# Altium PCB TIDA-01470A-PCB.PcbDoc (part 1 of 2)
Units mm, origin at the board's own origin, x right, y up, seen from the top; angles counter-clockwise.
Board outline 75 x 58 mm, 6 copper layers (Top Copper, Copper Layer 2, Copper Layer 3, Copper Layer 4, Copper Layer 5, Bottom Copper), stack 1.56 mm thick; 131 components, 70 nets, 308 pads, 94 vias.
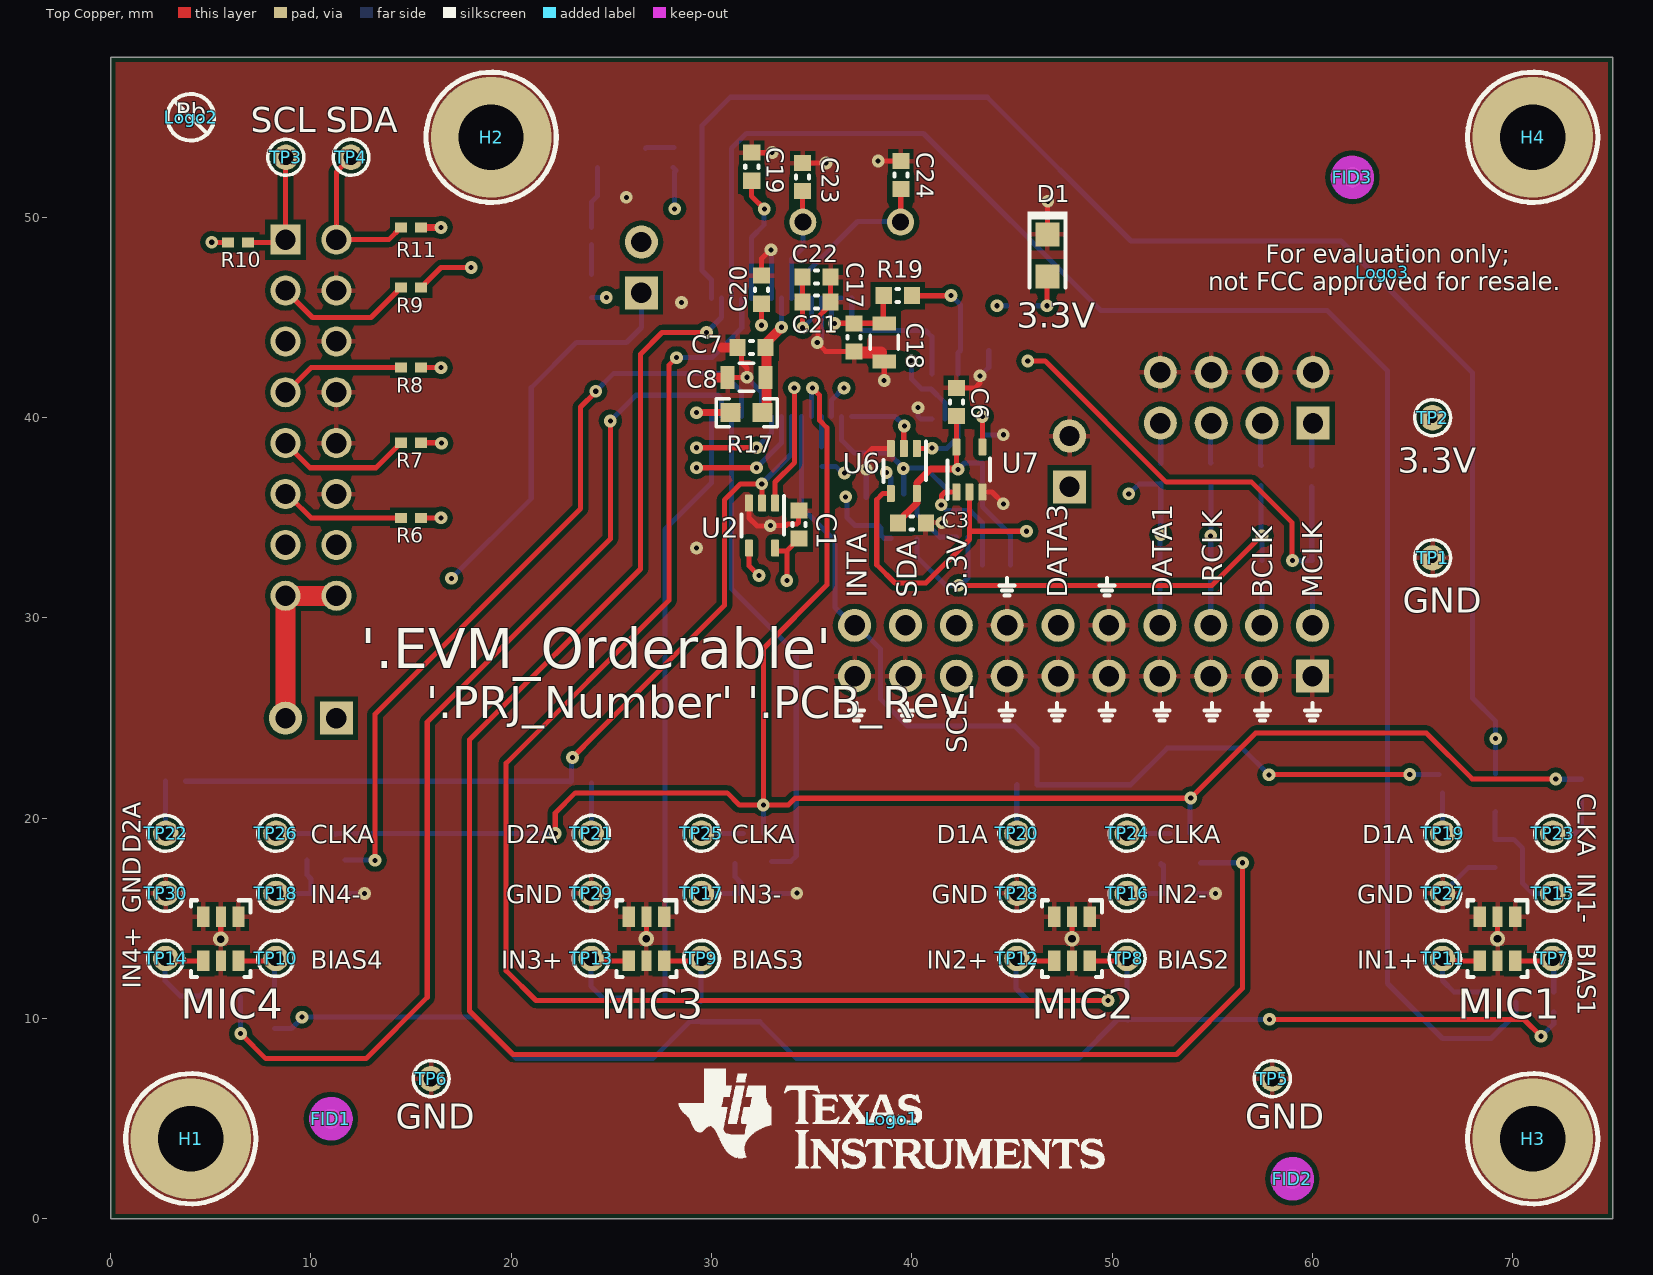
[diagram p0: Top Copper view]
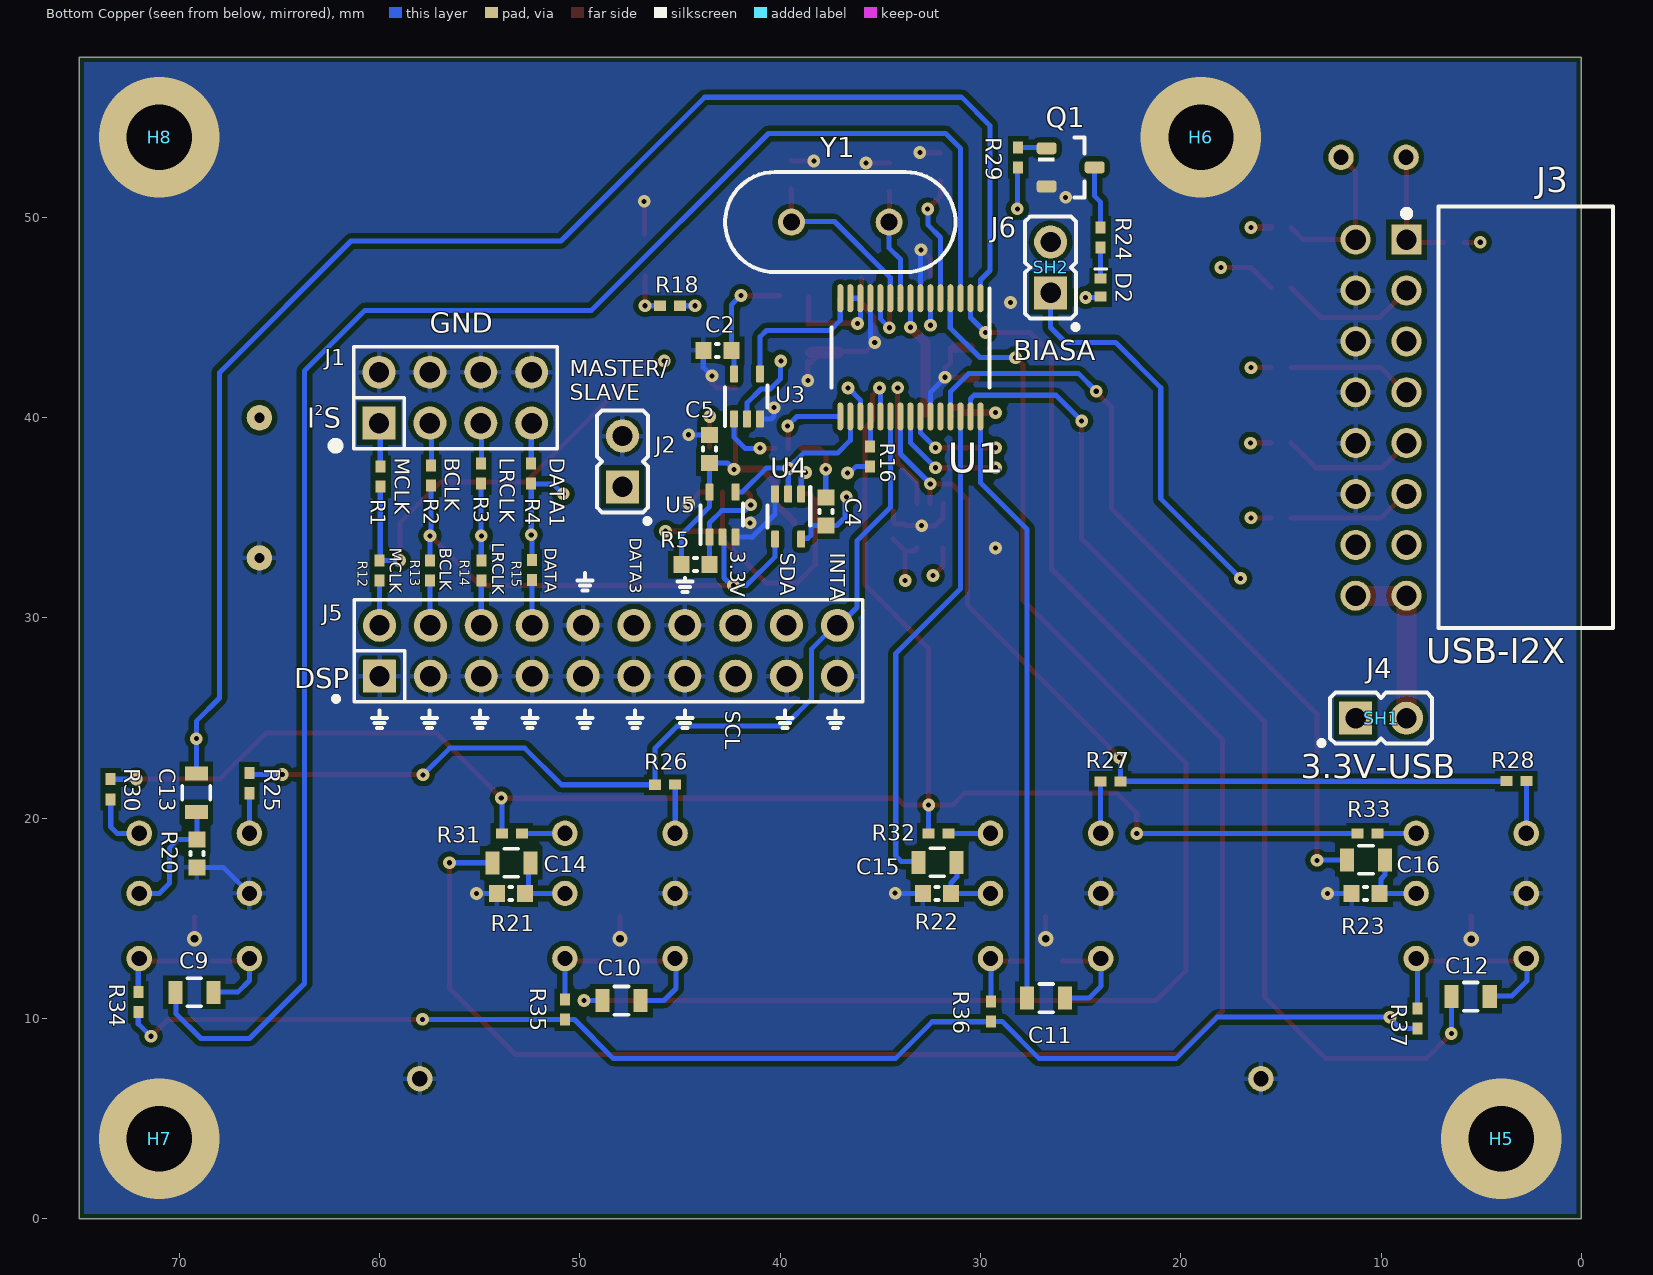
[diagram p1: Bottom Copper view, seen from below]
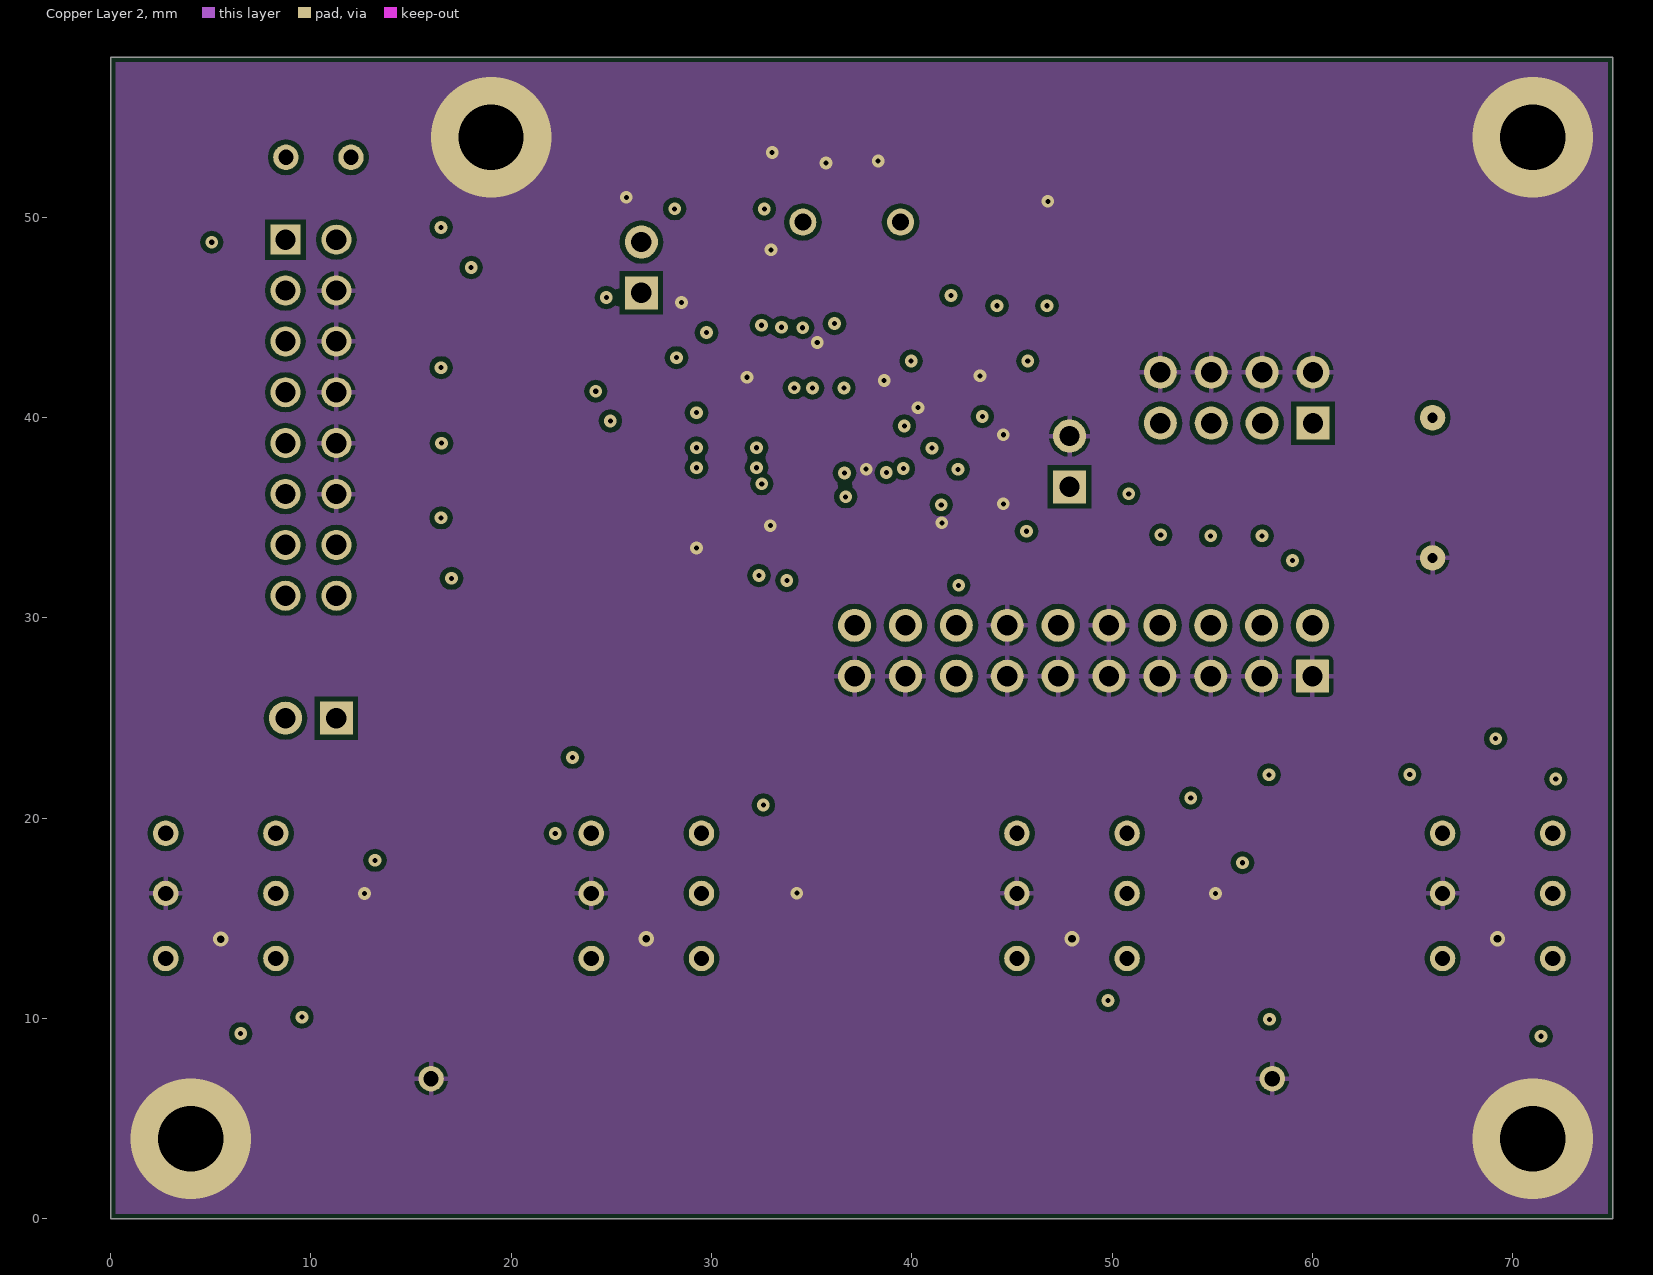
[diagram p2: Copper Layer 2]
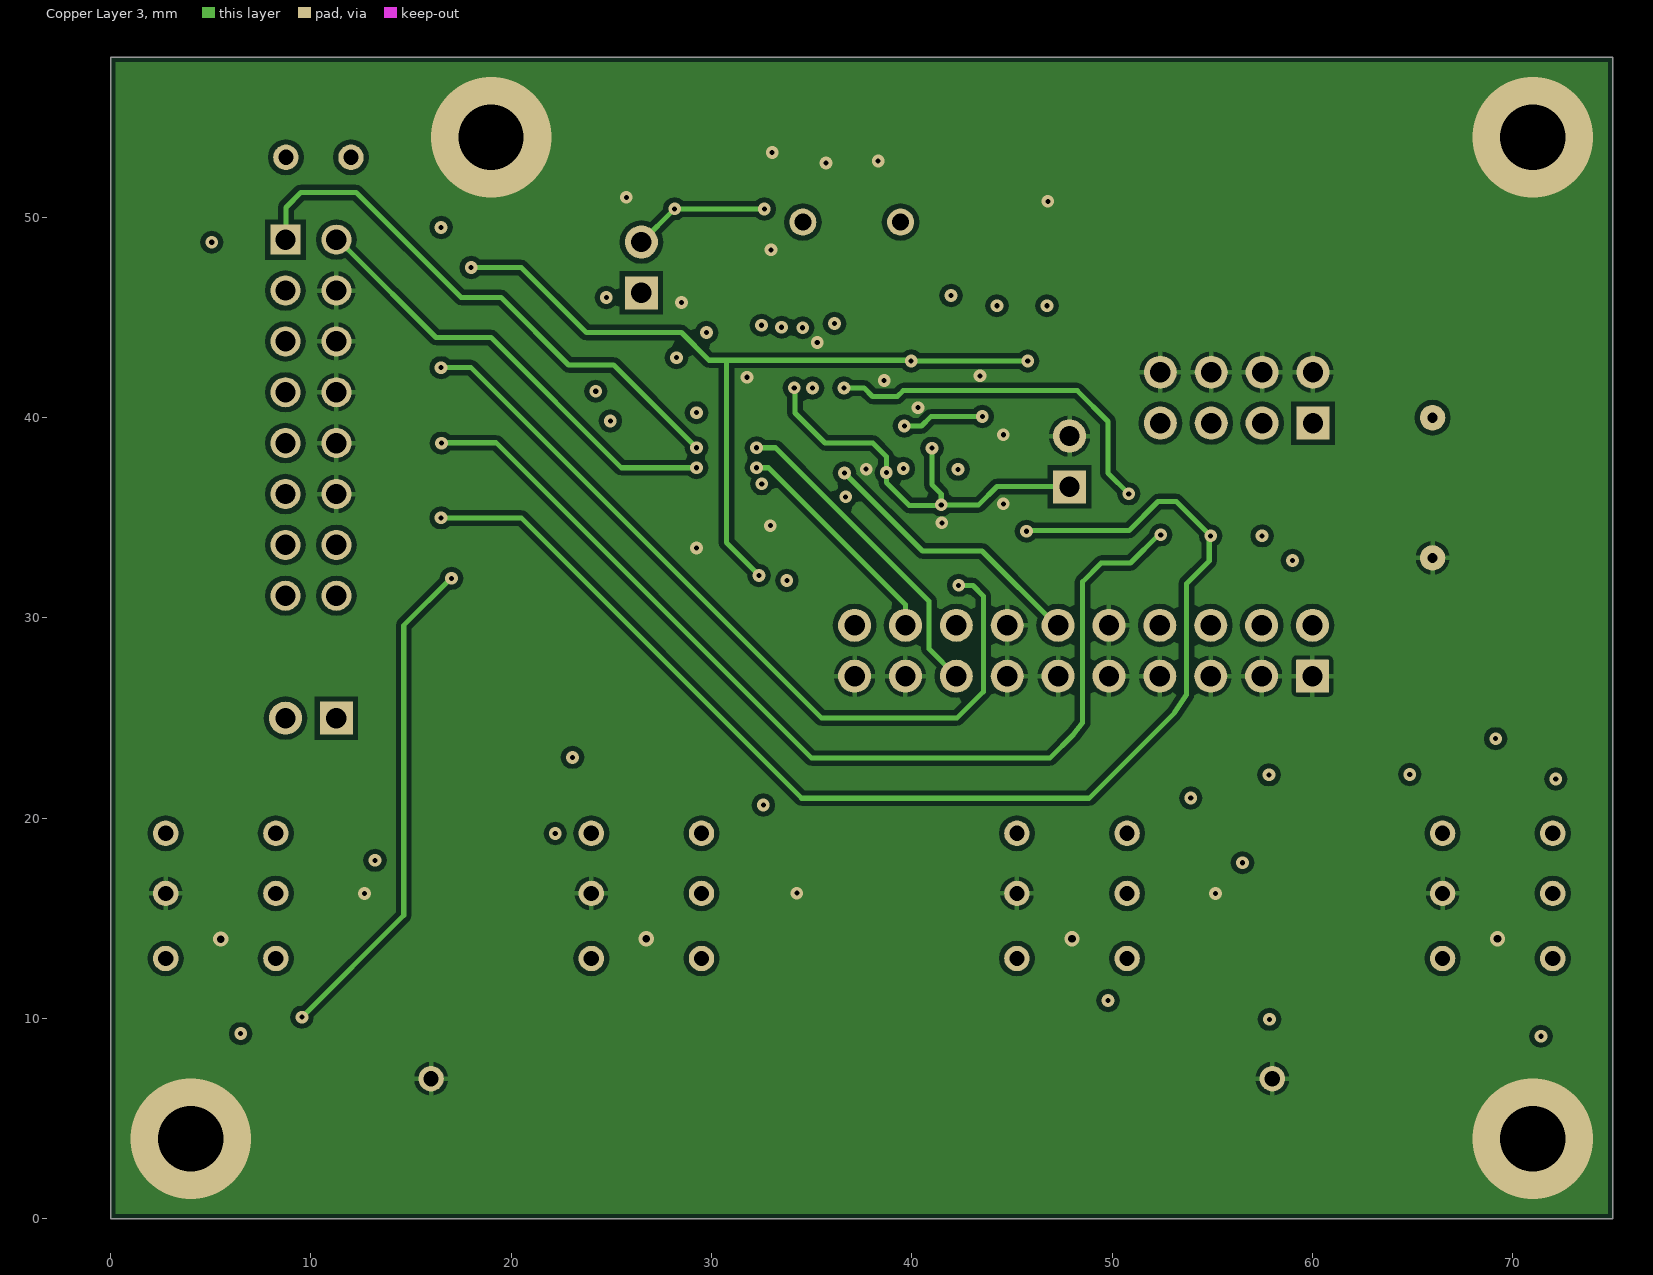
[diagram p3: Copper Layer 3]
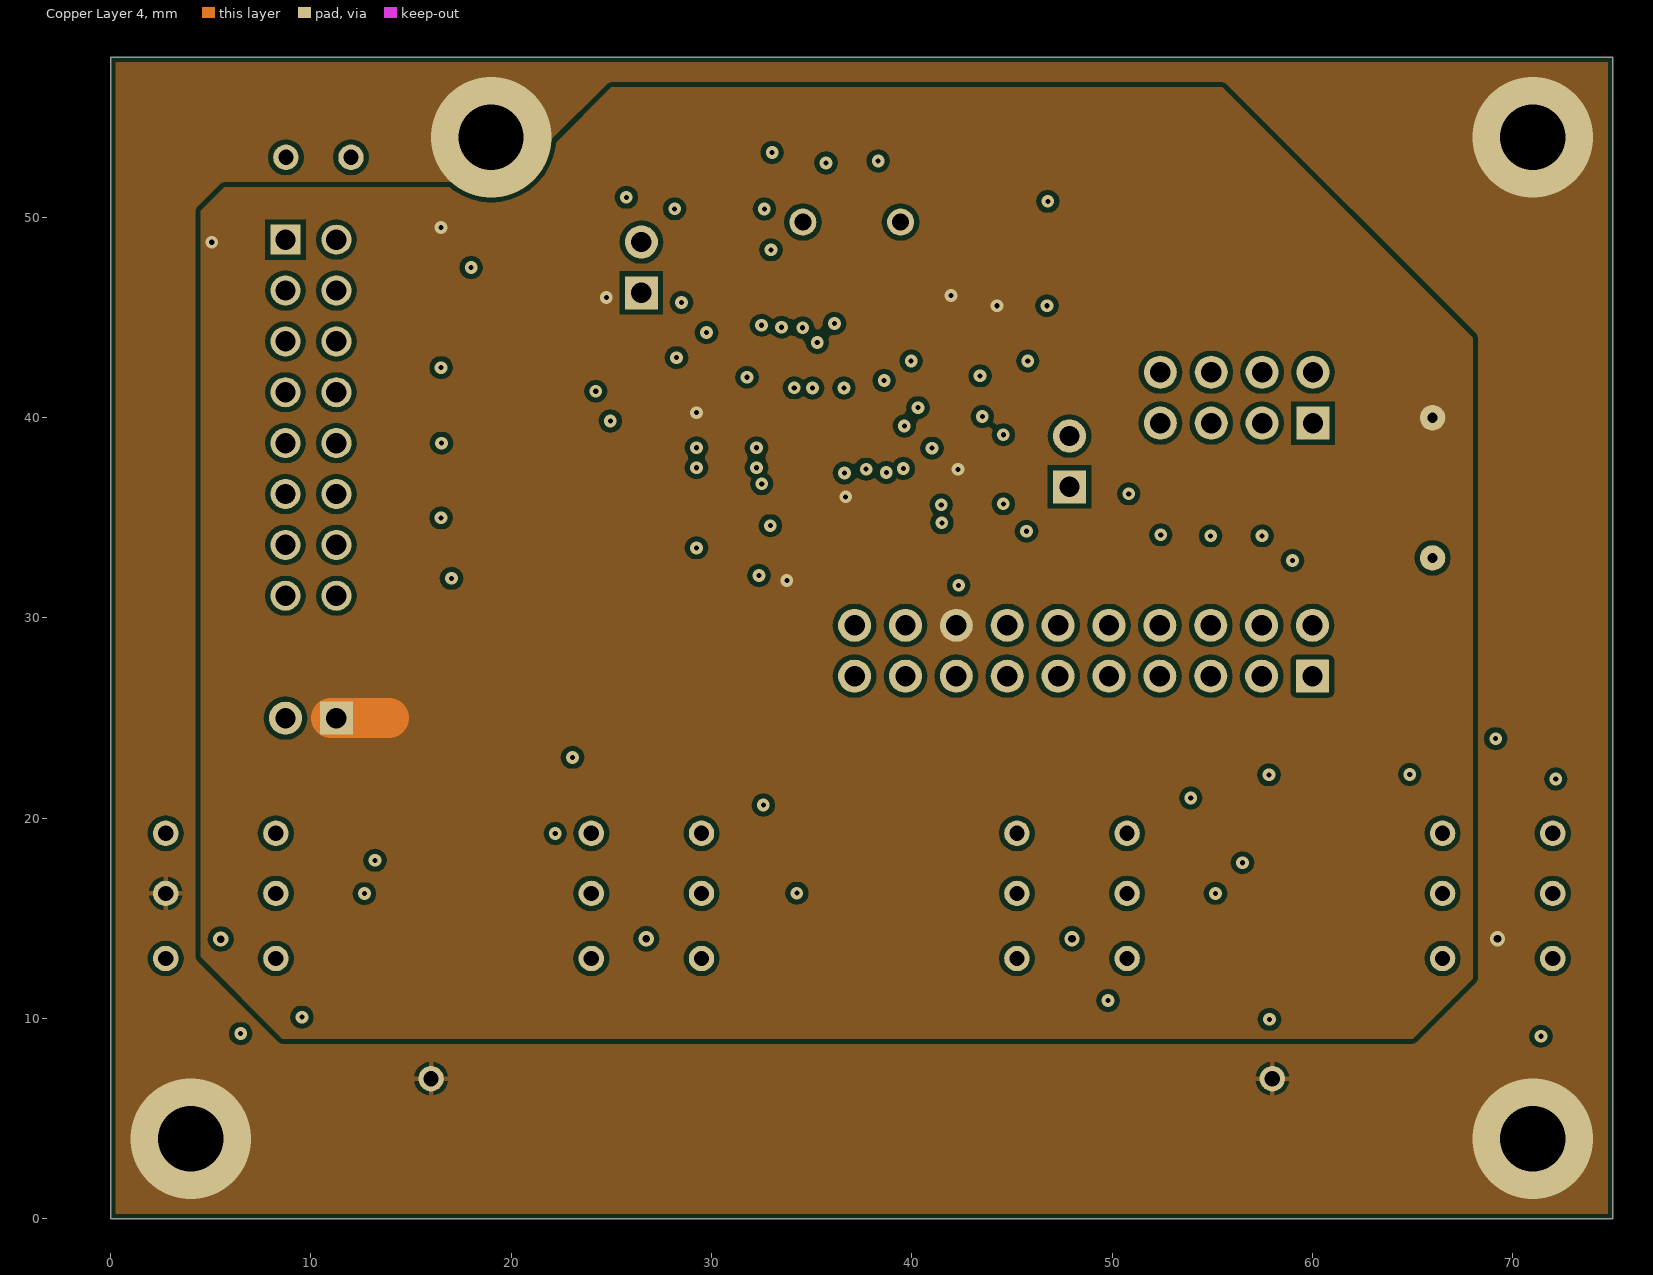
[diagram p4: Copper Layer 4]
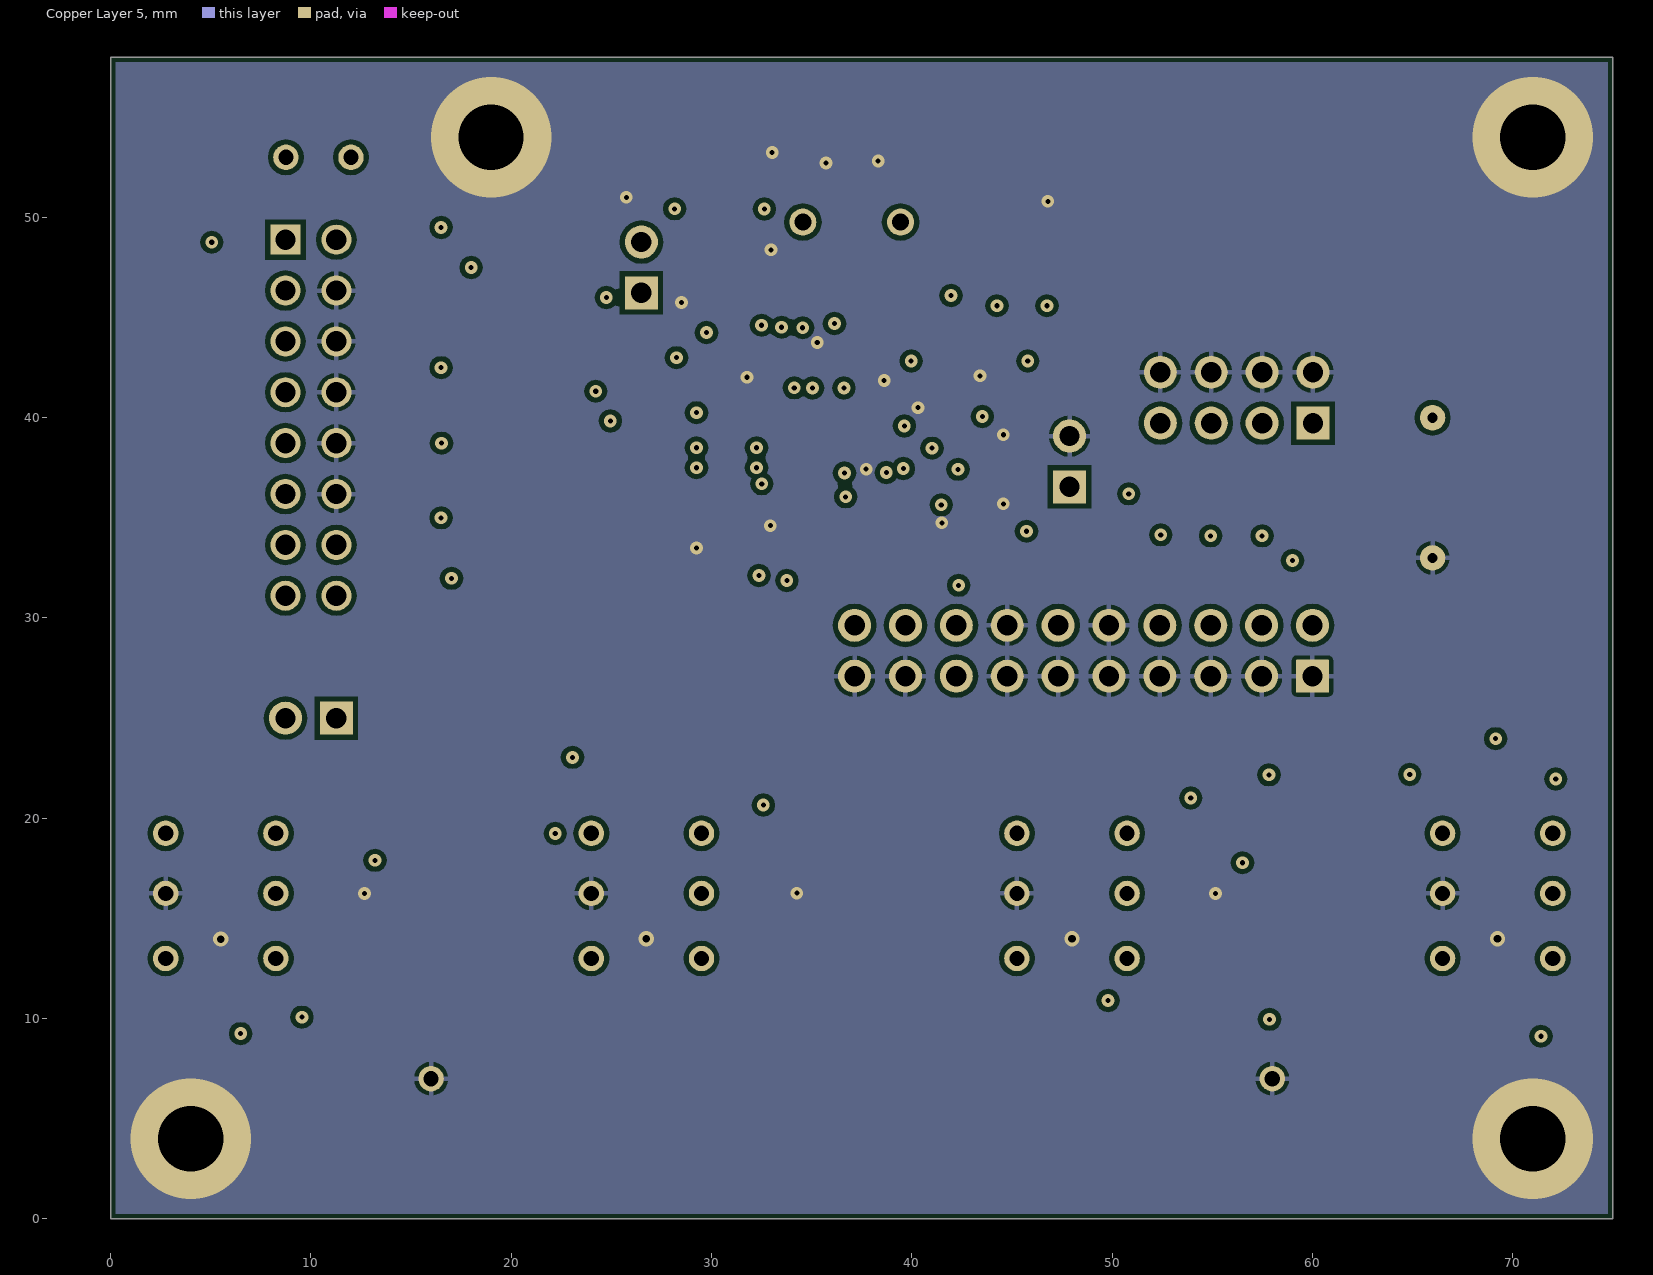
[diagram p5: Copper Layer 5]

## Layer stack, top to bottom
Top Solder Mask: solder mask 0.0127, Solder Resist, Dk 3.5
Top Copper: signal copper 0.0356
Dielectric 1: prepreg 0.1778, FR-4, Dk 4.2
Copper Layer 2: signal copper 0.0356
Dielectric 2: core 0.3556, FR-4, Dk 4.2
Copper Layer 3: signal copper 0.0356
Dielectric 4: prepreg 0.2794, FR-4, Dk 4.2
Copper Layer 4: signal copper 0.0356
Dielectric 5: core 0.3556, FR-4, Dk 4.2
Copper Layer 5: signal copper 0.0356
Dielectric 3: prepreg 0.1778, FR-4, Dk 4.2
Bottom Copper: signal copper 0.0356
Bottom Solder Mask: solder mask 0.0127, Solder Resist, Dk 3.5

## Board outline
0,0 75,0 75,58 0,58

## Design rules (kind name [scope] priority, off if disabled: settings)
AcuteAngle [All] p1: minimum=4.50000000000000E+0001 checktracksonly=FALSE
AssemblyTestPointUsage [All] p1: valid=2
BoardOutlineClearance BoardOutlineClearance_MountingHoles [OnCopper and InComponentClass('Mounting Holes')] p1: gap=1.016
BoardOutlineClearance BoardOutlineClearance_Poly [OnCopper and IsPoly] p2: gap=0.25
BoardOutlineClearance [OnCopper and Not InComponentClass('Logo') and not InComponentClass('FiducialMark') and not InRegion(1000,500,4000,800) and not InPoly] p3: gap=0.25
Clearance Clearance_Keepouts [((IsTrack Or IsArc) And Not InPoly) And IsFree and IsKeepOut vs ((IsTrack Or IsArc) And Not InPoly) And IsFree and IsKeepOut] p1: gap=0
Clearance Clearance_Poly [InPolygon] p2: gap=0.25
Clearance [All] p3: gap=0.2
ComponentClearance ComponentClearance_MountingHoles_FiducialMarks [InComponentClass('Mounting Holes') vs InComponentClass('FiducialMark')] p1: gap=1.27 collisioncheckmode=3 verticalgap=0.254 showdistances=FALSE
ComponentClearance ComponentClearance_Shunt [InComponentClass('Header') vs InComponentClass('Shunt')] p2: gap=0 collisioncheckmode=3 verticalgap=0 showdistances=FALSE
ComponentClearance ComponentClearance_Logo [InComponentClass('Logo')] p3: gap=0 collisioncheckmode=3 verticalgap=0 showdistances=FALSE
ComponentClearance ComponentClearance_ScrewToNut [(HasFootprint('NY PMS 440 0025 PH')) vs (HasFootprint('Keystone_1902C'))] p4: gap=0.127 collisioncheckmode=3 verticalgap=0.254 showdistances=FALSE
ComponentClearance ComponentClearance_MountingHoles [InComponentClass('Hardware') vs InComponentClass('Hardware')] p5: gap=0 collisioncheckmode=3 verticalgap=0 showdistances=FALSE
ComponentClearance ComponentClearance_SmallPassives [HasFootprint('0201*') or HasFootprint('0402*') or HasFootprint('0508') or HasFootprint('0603*') or HasFootprint('0612') or HasFootprint('0805*') or HasFootprint('0815*') or HasFootprint('0830*') or HasFootprint('1206*') or HasFootprint('1210*') or HasFootprint('1808*') or HasFootprint('1812*') or HasFootprint('1825*') or HasFootprint('2010*') or HasFootprint('2220*') or HasFootprint('2225*') or HasFootprint('2512*') or HasFootprint('2728*') or HasFootprint('3518*') or HasFootprint('DCK*') vs HasFootprint('0201*') or HasFootprint('0402*') or HasFootprint('0508') or HasFootprint('0603*') or HasFootprint('0612') or HasFootprint('0805*') or HasFootprint('0815*') or HasFootprint('0830*') or HasFootprint('1206*') or HasFootprint('1210*') or HasFootprint('1808*') or HasFootprint('1812*') or HasFootprint('1825*') or HasFootprint('2010*') or HasFootprint('2220*') or HasFootprint('2225*') or HasFootprint('2512*') or HasFootprint('2728*') or HasFootprint('3518*') or HasFootprint('DCK*')] p6: gap=0.25 collisioncheckmode=3 verticalgap=0 showdistances=FALSE
ComponentClearance ComponentClearance_THtoSMT [IsThruComponent vs IsSMTComponent] p7: gap=0.25 collisioncheckmode=3 verticalgap=0 showdistances=FALSE
ComponentClearance ComponentClearance_THtoTH [IsThruComponent vs IsThruComponent] p8: gap=0.762 collisioncheckmode=3 verticalgap=0.762 showdistances=FALSE
ComponentClearance [All] p9: gap=0.762 collisioncheckmode=3 verticalgap=0.254 showdistances=FALSE
DiffPairsRouting [All] p1: maxlimit=2.54 minlimit=0.254 mostfreqgap=0.254 toplayer_minwidth=0.381 toplayer_maxwidth=0.381 toplayer_prefwidth=0.381 midlayer1_minwidth=0.381 midlayer1_maxwidth=0.381 midlayer1_prefwidth=0.381 midlayer2_minwidth=0.381 midlayer2_maxwidth=0.381 midlayer2_prefwidth=0.381 midlayer3_minwidth=0.381 midlayer3_maxwidth=0.381 midlayer3_prefwidth=0.381 midlayer4_minwidth=0.381 midlayer4_maxwidth=0.381 midlayer4_prefwidth=0.381 bottomlayer_minwidth=0.381 bottomlayer_maxwidth=0.381 bottomlayer_prefwidth=0.381 maxuncoupledlength=25.4
FabricationTestPointUsage TestPointUsage [All] p1: valid=2 allowmultiple=FALSE
FabricationTestpoint Testpoint [All] p1: side=3 testpointundercomponent=TRUE minsize=1.016 maxsize=2.54 preferedsize=1.524 minholesize=0 maxholesize=1.016 preferedholesize=0.813 testpointgrid=0.025 allowsidetop=TRUE allowsidebottom=TRUE usegrid=TRUE gridtolerance=0
FanoutControl Fanout_LCC [IsLCC] p1: bgadir=Out bgaviamode=Centered fanoutstyle=Auto fanoutdirection=Alternating viagrid=0.025 // Fanout_LCC (Default Rule)
FanoutControl Fanout_BGA [IsBGA] p2: bgadir=Out bgaviamode=Centered fanoutstyle=Auto fanoutdirection=Alternating viagrid=0.025 // Fanout_BGA (Default Rule)
FanoutControl Fanout_Default [All] p4: bgadir=Out bgaviamode=Centered fanoutstyle=Auto fanoutdirection=Alternating viagrid=0.025 // Fanout_Default (Default Rule)
FanoutControl Fanout_Small [(CompPinCount < 5)] p5: bgadir=Out bgaviamode=Centered fanoutstyle=Auto fanoutdirection=OutThenIn viagrid=0.025 // Fanout_Small (Default Rule)
HoleSize [All] p1: absolutevalues=TRUE maxlimit=6.375 minlimit=0.2 maxpercent=80.000 minpercent=20.000
MinimumAnnularRing MinimumAnnularRing_ThermalPadVias [IsVia and InAnyComponent] p1: minimumring=0.15
MinimumAnnularRing [All] p2: minimumring=0.127
MinimumSolderMaskSliver MinimumSolderMaskSliver_Logo [InComponentClass('Logo') vs InComponentClass('Logo')] p1: minsoldermaskwidth=0.018
MinimumSolderMaskSliver [All] p2: minsoldermaskwidth=0.089
PlaneConnect [All] p1: planeconnectstyle=Relief reliefexpansion=0.254 reliefentries=4 reliefconductorwidth=0.254 reliefairgap=0.254
PolygonConnect "GND Thermals 0.25mm" [(InComponent('BIAS*') or InComponent('C*') or InComponent('D*') or InComponent('GND*') or InComponent('I2S*') or InComponent('J*') or InComponent('MIC*') or InComponent('R*') or InComponent('TP*') or InComponent('USB-I2X')) vs InNet('GND')] p1: connectstyle=Relief reliefconductorwidth=0.25 reliefentries=4 polygonreliefangle="90 Angle" airgapwidth=0.2
PolygonConnect PreFlood [All] p2: connectstyle=Direct reliefconductorwidth=0.254 reliefentries=4 polygonreliefangle="90 Angle" airgapwidth=0.254
RoutingVias ThermalPadVias [IsVia and InAnyComponent] p1: holewidth=0.2 width=0.5 viastyle="Through Hole" minholewidth=0.2 minwidth=0.5 maxholewidth=0.33 maxwidth=0.6
RoutingVias [All] p2: holewidth=0.254 width=0.635 viastyle="Through Hole" minholewidth=0.254 minwidth=0.508 maxholewidth=3.25 maxwidth=6
SilkToBoardRegionClearance [Not ((IsComment or IsDesignator) And (Hide <> 'False')) and not InRegion(1000,500,4000,800)] p1:
SilkToSilkClearance SilkToSilkClearance_Pb-FreeLogo [(HasFootprint('Pb-Free_Overlay_Medium') OR HasFootprint('Pb-Free_Overlay_Small')) vs (HasFootprint('Pb-Free_Overlay_Medium') OR HasFootprint('Pb-Free_Overlay_Small'))] p1: silktosilkclearance=0
SilkToSilkClearance [All] p2: silktosilkclearance=0.127
SilkToSolderMaskClearance SilkToComponentPadClearance [IsPad and InAnycomponent] p1: minsilkscreentomaskgap=0.127 clearancetoexposedcopper=TRUE
SilkToSolderMaskClearance "Silk to Solder Mask Opening" [All] p2: minsilkscreentomaskgap=0.127 clearancetoexposedcopper=FALSE
SolderMaskExpansion [All] p1: expansion=0.05
Width [All] p1: maxlimit=2.54 minlimit=0.152 preferedwidth=0.254 checkconnectedcopper=TRUE
15 further rules are at their usual default settings.

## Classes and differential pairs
component class Shunt: SH1 SH2
component class Header: J1 J2 J4 J5 J6
component class Logo: Logo1
component class Hardware: H1 H2 H3 H4 H5 H6 H7 H8
component class FiducialMark: FID1 FID2 FID3
component class AssemblyNote: ZZ1 ZZ2 ZZ3
component class TIDA-01470A_Hardware: !PCB FID1 FID2 FID3 H1 H2 H3 H4 H5 H6 H7 H8 H9 Logo1 Logo2 Logo3 SH1 SH2 ZZ1 ZZ2 ZZ3
component class TIDA-01470A_Main-IO: C7 C8 C9 C10 C11 C12 C13 C14 C15 C16 C17 C18 C19 C20 C21 C22 C23 C24 D1 D2 J6 MIC1 MIC2 MIC3 MIC4 Q1 R17 R18 R19 R20 R21 R22 R23 R24 R25 R26 R27 R28 R29 R30 R31 R32 R33 R34 R35 R36 R37 TP7 TP8 TP9 TP10 TP11 TP12 TP13 TP14 TP15 TP16 TP17 TP18 TP19 TP20 TP21 TP22 TP23 TP24 TP25 TP26 TP27 TP28 TP29 TP30 U1 Y1

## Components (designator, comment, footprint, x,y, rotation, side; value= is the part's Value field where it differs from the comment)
C1 "GRM188R71C104KA01D" 0603L 34.375,34.665 r270 top
C2 "GRM188R71C104KA01D" 0603L 43.14,43.36 r180 bottom
C3 "GRM188R71C104KA01D" 0603L 40,34.75 r180 top
C4 "GRM188R71C104KA01D" 0603L 37.725,35.315 r270 bottom
C5 "GRM188R71C104KA01D" 0603L 43.525,38.44 r270 bottom
C6 "GRM188R71C104KA01D" 0603L 42.225,40.79 r270 top
C7 "GRM188R71C104KA01D" 0603L 32,43.515 r0 top
C8 "GRM21BR71A106KE51K" 0805_KTR 31.75,42.015 r0 top
C9 "GRM21BR71A106KE51K" 0805_KTR 69.25,11.31 r180 bottom
C10 "GRM21BR71A106KE51K" 0805_KTR 47.925,10.9 r180 bottom
C11 "GRM21BR71A106KE51K" 0805_KTR 26.725,11.025 r180 bottom
C12 "GRM21BR71A106KE51K" 0805_KTR 5.525,11.1 r180 bottom
C13 "GRM21BR71A106KE51K" 0805_KTR 69.15,21.275 r270 bottom
C14 "GRM21BR71A106KE51K" 0805_KTR 53.425,17.775 r180 bottom
C15 "GRM21BR71A106KE51K" 0805_KTR 32.15,17.8 r180 bottom
C16 "GRM21BR71A106KE51K" 0805_KTR 10.75,17.925 r180 bottom
C17 "GRM188R71C104KA01D" 0603L 37.125,44.015 r90 top
C18 "GRM21BR71A106KE51K" 0805_KTR 38.625,43.765 r90 top
C19 "GRM188R71C104KA01D" 0603L 32.01,52.53 r270 top
C20 "GRM188R71C105KA12D" 0603L 32.5,46.39 r90 top
C21 "GRM188R71C104KA01D" 0603L 35.25,45.765 r180 top
C22 "GRM188R71C105KA12D" 0603L 35.25,47.015 r0 top
C23 "GRM1885C1H180JA01D" 0603L 34.55,52.015 r90 top
C24 "GRM1885C1H180JA01D" 0603L 39.45,52.115 r90 top
D1 "3.3V" LED_LTST-C171 46.775,48.105 r90 top
D2 "BIASA" LED_SMLP12_BLUE 24,46.5 r90 bottom
FID1 "Fiducial" Fiducial10-20 11,5 r90 top
FID2 "Fiducial" Fiducial10-20 59,2 r90 top
FID3 "Fiducial" Fiducial10-20 62,52 r90 top
H1 "M3" BuildingFastener_MPMS_003_0005_PH 4,4 r90 top
H2 "M3" BuildingFastener_MPMS_003_0005_PH 19,54 r90 top
H3 "M3" BuildingFastener_MPMS_003_0005_PH 71,4 r90 top
H4 "M3" BuildingFastener_MPMS_003_0005_PH 71,54 r90 top
H5 "24438" Keystone24438 4,4 r270 bottom
H6 "24438" Keystone24438 19,54 r270 bottom
H7 "24438" Keystone24438 71,4 r270 bottom
H8 "24438" Keystone24438 71,54 r270 bottom
J1 "I²S" CONN_PEC04DAAN 56.22,41 r180 bottom
J2 "Master/Slave" Sullins_PBC02SAAN 47.875,37.815 r0 bottom
J3 "USB-I2X" Sullins_PPPC082LJBN-RC 10,40 r90 bottom locked
J4 "3.3V-USB" Sullins_PBC02SAAN 10,25 r90 bottom
J5 "DSP" TSW-110-07-G-D 48.575,28.365 r180 bottom locked
J6 "BIASA" Sullins_PBC02SAAN 26.5,47.5 r0 bottom
Logo1 "Texas Instruments" TI_Stacked_Overlay_Small 39,5 r0 top
Logo2 "Pb-Free Symbol" Pb-Free_Overlay_Small 4,55 r0 top
Logo3 "FCC disclaimer" FCC_disclaimer_stacked 63.5,47.25 r0 top
MIC1 "SPH1642HT5H-1" Knowles_SPH1642HT5H-1 69.25,14.75 r270 top locked
MIC2 "SPH1642HT5H-1" Knowles_SPH1642HT5H-1 48,14.75 r270 top locked
MIC3 "SPH1642HT5H-1" Knowles_SPH1642HT5H-1 26.75,14.75 r270 top locked
MIC4 "SPH1642HT5H-1" Knowles_SPH1642HT5H-1 5.5,14.75 r270 top locked
Q1 "MMBT2222A" SOT-23 25.5,52.5 r180 bottom
R1 "RC0402FR-0749R9L" 0402L 59.955,37.06 r90 bottom
R2 "RC0402FR-0749R9L" 0402L 57.43,37.11 r90 bottom
R3 "RC0402FR-0749R9L" 0402L 54.93,37.21 r90 bottom
R4 "RC0402FR-0749R9L" 0402L 52.43,37.21 r90 bottom
R5 "ERJ-3EKF1002V" 0603L 44.23,32.66 r0 bottom
R6 "RC0402FR-0749R9L" 0402L 15,35 r180 top
R7 "RC0402FR-0749R9L" 0402L 15,38.75 r180 top
R8 "RC0402FR-0749R9L" 0402L 15,42.5 r180 top
R9 "RC0402FR-0749R9L" 0402L 15,46.5 r180 top
R10 "CRCW04022K21FKED" 0402L 6.37,48.75 r0 top
R11 "CRCW04022K21FKED" 0402L 15,49.5 r180 top
R12 "RC0402FR-0749R9L" 0402L 60,32.365 r270 bottom
R13 "RC0402FR-0749R9L" 0402L 57.475,32.365 r270 bottom
R14 "RC0402FR-0749R9L" 0402L 54.925,32.365 r270 bottom
R15 "RC0402FR-0749R9L" 0402L 52.4,32.39 r270 bottom
R16 "RC0402FR-0749R9L" 0402L 35.51,38.07 r270 bottom
R17 "CRCW06030000Z0EA" 0603 31.75,40.25 r0 top
R18 "CRCW0402360RJNED" 0402L 45.5,45.59 r180 bottom
R19 "CRCW06030000Z0EA" 0603L 39.3,46.09 r180 top
R20 "CRCW06030000Z0EA" 0603L 69.125,18.25 r270 bottom
R21 "CRCW06030000Z0EA" 0603L 53.45,16.25 r0 bottom
R22 "CRCW06030000Z0EA" 0603L 32.175,16.25 r0 bottom
R23 "CRCW06030000Z0EA" 0603L 10.775,16.25 r0 bottom
R24 "ERJ-2RKF1000X" 0402L 24,49 r90 bottom
R25 "RC0402FR-0749R9L" 0402L 66.5,21.75 r270 bottom
R26 "RC0402FR-0749R9L" 0402L 45.75,21.675 r180 bottom
R27 "RC0402FR-0749R9L" 0402L 23.52,21.84 r0 bottom
R28 "RC0402FR-0749R9L" 0402L 3.25,21.85 r180 bottom
R29 "CRCW04022K15FKED" 0402L 28.125,53 r270 bottom
R30 "RC0402FR-0749R9L" 0402L 73.425,21.45 r270 bottom
R31 "RC0402FR-0749R9L" 0402L 53.4,19.25 r180 bottom
R32 "RC0402FR-0749R9L" 0402L 32.1,19.25 r180 bottom
R33 "RC0402FR-0749R9L" 0402L 10.675,19.25 r180 bottom
R34 "CRCW04022K21FKED" 0402L 72.05,10.82 r90 bottom
R35 "CRCW04022K21FKED" 0402L 50.75,10.45 r90 bottom
R36 "CRCW04022K21FKED" 0402L 29.475,10.35 r90 bottom
R37 "CRCW04022K21FKED" 0402L 8.175,10 r90 bottom
SH1 "SNT-100-BK-G" SNT-100-BK-G 10,25 r180 bottom
SH2 "SNT-100-BK-G" SNT-100-BK-G 26.5,47.5 r270 bottom
TP1 "GND" TestPoint_50x20-TH 66,33 r180 top
TP2 "3.3V" TestPoint_50x20-TH 66,40 r180 top
TP3 "SCL" TestPoint_50x30-TH 8.75,53 r0 top
TP4 "SDA" TestPoint_50x30-TH 12,53 r0 top
TP5 "GND" TestPoint_50x30-TH 58,7 r90 top
TP6 "GND" TestPoint_50x30-TH 16,7 r90 top
TP7 "BIAS1" TestPoint_50x30-TH 72,13 r180 top
TP8 "BIAS2" TestPoint_50x30-TH 50.75,13 r180 top
TP9 "BIAS3" TestPoint_50x30-TH 29.5,13 r90 top
TP10 "BIAS4" TestPoint_50x30-TH 8.25,13 r180 top
TP11 "IN1+" TestPoint_50x30-TH 66.5,13 r90 top
TP12 "IN2+" TestPoint_50x30-TH 45.25,13 r90 top
TP13 "IN3+" TestPoint_50x30-TH 24,13 r90 top
TP14 "IN4+" TestPoint_50x30-TH 2.75,13 r180 top
TP15 "IN1-" TestPoint_50x30-TH 72,16.25 r90 top
TP16 "IN2-" TestPoint_50x30-TH 50.75,16.25 r90 top
TP17 "IN3-" TestPoint_50x30-TH 29.5,16.25 r90 top
TP18 "IN4-" TestPoint_50x30-TH 8.25,16.25 r180 top
TP19 "D1A" TestPoint_50x30-TH 66.5,19.25 r90 top
TP20 "D1A" TestPoint_50x30-TH 45.25,19.25 r90 top
TP21 "D2A" TestPoint_50x30-TH 24,19.25 r90 top
TP22 "D2A" TestPoint_50x30-TH 2.75,19.25 r90 top
TP23 "CLKA" TestPoint_50x30-TH 72,19.25 r90 top
TP24 "CLKA" TestPoint_50x30-TH 50.75,19.25 r90 top
TP25 "CLKA" TestPoint_50x30-TH 29.5,19.25 r90 top
TP26 "CLKA" TestPoint_50x30-TH 8.25,19.25 r180 top
TP27 "GND" TestPoint_50x30-TH 66.5,16.25 r90 top
TP28 "GND" TestPoint_50x30-TH 45.25,16.25 r90 top
TP29 "GND" TestPoint_50x30-TH 24,16.25 r90 top
TP30 "GND" TestPoint_50x30-TH 2.75,16.25 r90 top
U1 "PCM1864DBTR" DBT0030A_N 33.5,43.015 r270 bottom locked
U2 "LVC1G125" DCK0005A_N 32.525,34.615 r270 top
U3 "LVC1G126" DCK0005A_N 41.65,41.065 r90 bottom
U4 "LVC1G125" DCK0005A_N 39.6,35.065 r270 bottom
U5 "LVC1G126" DCK0005A_N 42.875,35.165 r90 bottom
U6 "LVC1G125" DCK0005A_N 39.6,37.34 r270 top
U7 "LVC1G126" DCK0005A_N 42.875,37.415 r90 top
Y1 "9B-24.576MEEJ-B" TXC_9B 37,49.765 r0 bottom locked
ZZ1 "These assemblies are ESD sensitive, ESD precautions shall be observed." AssemblyNote -7.5,67.5 r0 top
ZZ2 "These assemblies must be clean and free from flux and all contaminants. Use of no clean flux is not acceptable." AssemblyNote -7.5,65 r0 top
ZZ3 "These assemblies must comply with workmanship standards IPC-A-610 Class 2, unless otherwise specified." AssemblyNote -7.5,62.5 r0 top

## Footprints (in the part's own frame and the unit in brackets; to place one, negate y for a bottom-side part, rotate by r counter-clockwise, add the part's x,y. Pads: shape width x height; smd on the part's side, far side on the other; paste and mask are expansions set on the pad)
0402L [mm] "0402 from SM-752 data"
  rect 0.6x0.5 smd: 1(-0.5,0) 2(0.5,0)
  body extent -0.55,-0.3 0.55,0.3, height 0.6
0603 [mm] "0603 from SM-752 data"
  rect 1x0.95 smd: 1(-0.8,0) 2(0.8,0)
  silkscreen extent -1.52,-0.69 1.52,0.69, body extent -0.87,-0.47 0.87,0.47, height 1
0603L [mm] "0603 from SM-752 data"
  rect 0.8x0.85 smd: 1(-0.7,0) 2(0.7,0)
  silkscreen extent -0.07,-0.33 0.07,0.33, body extent -0.87,-0.47 0.87,0.47, height 1
0805_KTR [mm] "ROHM"
  rect 0.7x1.15 smd: 1(-0.95,0) 2(0.95,0)
  silkscreen extent -0.35,-0.7 0.35,0.7, body extent -1.05,-0.67 1.05,0.67, height 0.65
AssemblyNote [mm] "Assembly Note"
BuildingFastener_MPMS_003_0005_PH [mil] "MACHINE SCREW PAN PHILLIPS M3"
  round 1 on Mech3: 0(0,0)
  body extent -118,-118 118,118, height 93
CONN_PEC04DAAN [mm] "SULLINS"
  rect 1.65x1.65 hole 1.016 mask+0: 1(-3.81,-1.27)
  round 1.65 hole 1.016 mask+0: 2(-3.81,1.27) 3(-1.27,-1.27) 4(-1.27,1.27) 5(1.27,-1.27) 6(1.27,1.27) 7(3.81,-1.27) 8(3.81,1.27)
  silkscreen extent -6.18,-2.6 5.08,2.54, body extent -5.08,-2.54 5.08,2.54, height 8.38
DBT0030A_N [mm] "TSSOP, 30-Leads, Body 7.8x4.4mm, Pitch 0.5mm, IPC Medium Density"
  oval 1.4x0.3 smd: 1(-2.95,3.5) 2(-2.95,3) 3(-2.95,2.5) 4(-2.95,2) 5(-2.95,1.5) 6(-2.95,1) 7(-2.95,0.5) 8(-2.95,0) 9(-2.95,-0.5) 10(-2.95,-1) 11(-2.95,-1.5) 12(-2.95,-2) 13(-2.95,-2.5) 14(-2.95,-3) 15(-2.95,-3.5) 16(2.95,-3.5) 17(2.95,-3) 18(2.95,-2.5) 19(2.95,-2) 20(2.95,-1.5) 21(2.95,-1) 22(2.95,-0.5) 23(2.95,0) 24(2.95,0.5) 25(2.95,1) 26(2.95,1.5) 27(2.95,2) 28(2.95,2.5) 29(2.95,3) 30(2.95,3.5)
  silkscreen extent -3.42,-3.95 1.5,3.95, body extent -3.21,-3.9 3.21,3.9, height 1.2
DCK0005A_N [mm] "SOT353, 5-Leads, Body 2x1.3mm, Pitch 0.65mm, Lead Span 2.1mm, IPC Medium Density"
  rrect25% 0.85x0.4 smd: 1(-1.125,0.65) 2(-1.125,0) 3(-1.125,-0.65) 4(1.125,-0.65) 5(1.125,0.65)
  silkscreen extent -1.48,-1.02 0.55,1.1, body extent -1.14,-1 1.14,1, height 0.95
FCC_disclaimer_stacked [mm]
Fiducial10-20 [mm]
  round 1 smd mask+0.5: 1(0,0)
  Top Copper keep-out circle w1.178: c0,0 r0.5
Keystone24438 [mil] "Standoff, Aluminium, M3x0.5mm, L 25 mm"
  round 1 on Mech4: 0(0,0)
  body extent -98,-114 98,114, height 984
Knowles_SPH1642HT5H-1 [mm] "SMD, 6-Leads, Body 3.5x2.65mm"
  rect 1.032x0.622 smd: 1(-0.342,0.884) 3(-0.342,-0.884) 4(1.866,-0.884) 6(1.866,0.884)
  rect 1.032x0.5 smd: 2(-0.342,0) 5(1.866,0)
  silkscreen extent -1.16,-1.5 2.68,1.5, body extent -1.04,-1.38 2.56,1.38, height 1.1
LED_LTST-C171 [mm] "LITE-ON"
  rect 1.2x1.2 smd: 1(-1.05,0) 2(1.05,0)
  silkscreen extent -1.6,-1 2.2,1, body extent -1.05,-0.67 1.05,0.67, height 0.8
LED_SMLP12_BLUE [mm] "Rohm Semiconductor"
  rect 0.5x0.6 smd mask+0.08: 1(-0.45,0) 2(0.45,0)
  silkscreen extent 0.92,-0.3 0.92,0.3, body extent -0.55,-0.35 0.55,0.35, height 0.25
Pb-Free_Overlay_Small [mm]
  silkscreen extent -1.16,-1.17 1.17,1.17
SNT-100-BK-G [mil] "Samtec STEP model"
  round 1 on Mech4: 0(0,0)
  body extent -100,-50 100,50, height 344
SOT-23 [mm] "SOT23, 3-Leads, Body 2.9x1.3mm, Pitch 0.95mm, Lead Span 2.5mm, IPC Medium Density"
  rrect50% 1x0.6 smd: 1(-1.2,0.95) 2(-1.2,-0.95) 3(1.2,0)
  silkscreen extent -1.62,-1.5 0.7,1.5, body extent -1.16,-1.45 1.21,1.45, height 1
Sullins_PBC02SAAN [mm] "Sullins 100mil, 1x2, 230 mil above insulator"
  rect 1.65x1.65 hole 1.016: 1(0,1.27)
  round 1.65 hole 1.016: 2(0,-1.27)
  silkscreen extent -1.37,-2.54 1.27,3.1, body extent -1.27,-2.54 1.27,2.54, height 8.38
Sullins_PPPC082LJBN-RC [mm] "Sullins Electronics"
  rect 1.5x1.5 hole 1.016 paste+0: 1(8.89,-1.27)
  round 1.5 hole 1.016 paste+0: 2(8.89,1.27) 3(6.35,-1.27) 4(6.35,1.27) 5(3.81,-1.27) 6(3.81,1.27) 7(1.27,-1.27) 8(1.27,1.27) 9(-1.27,-1.27) 10(-1.27,1.27) 11(-3.81,-1.27) 12(-3.81,1.27) 13(-6.35,-1.27) 14(-6.35,1.27) 15(-8.89,-1.27) 16(-8.89,1.27)
  silkscreen extent -10.51,-11.57 10.54,-1.14, body extent -10.41,-11.37 10.41,1.58, height 5.08
TestPoint_50x20-TH [mil] "Thru Hole Test Point, 50mil Pad, 20mil Drill"
  round 50 hole 20: 1(0,0)
  silkscreen extent -35,-35 35,35, body extent -25,-25 25,25, height 50
TestPoint_50x30-TH [mil] "Thru Hole Test Point, 50mil Pad, 20mil Drill"
  round 50 hole 30: 1(0,0)
  silkscreen extent -35,-35 35,35, body extent -25,-25 25,25, height 50
TI_Stacked_Overlay_Small [mm]
  silkscreen extent -10.63,-2.49 10.63,2.49
TSW-110-07-G-D [mm] "Samtec 100mil, 2x10, 230 mil above insulator"
  rrect6% 1.65x1.65 hole 1.016: 1(-11.43,-1.27)
  round 1.65 hole 1.016: 2(-11.43,1.27) 3(-8.89,-1.27) 4(-8.89,1.27) 5(-6.35,-1.27) 6(-6.35,1.27) 7(-3.81,-1.27) 8(-3.81,1.27) 9(-1.27,-1.27) 10(-1.27,1.27) 11(1.27,-1.27) 12(1.27,1.27) 13(3.81,-1.27) 14(3.81,1.27) 15(6.35,-1.27) 16(6.35,1.27) 17(8.89,-1.27) 18(8.89,1.27) 19(11.43,-1.27) 20(11.43,1.27)
  silkscreen extent -13.73,-2.54 12.7,2.54, body extent -12.7,-2.54 12.7,2.54, height 8.38
TXC_9B [mm] "TH, 2-Leads, Body 11.5x5mm, Pin Spacing 4.88mm"
  round 1.35 hole 0.85: 1(-2.44,0) 2(2.44,0)
  silkscreen extent -5.75,-2.5 5.75,2.5, body extent -5.75,-2.5 5.75,2.5, height 3.68

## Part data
C1 C2 C3 C4 C5 C6 C7 C17 C19 C21: "CAP, CERM, 0.1 µF, 16 V, +/- 10%, X7R, 0603"
C8 C9 C10 C11 C12 C13 C14 C15 C16 C18: "CAP, CERM, 10 µF, 10 V, +/- 10%, X7R, 0805"
C20 C22: "CAP, CERM, 1 µF, 16 V, +/- 10%, X7R, 0603"
C23 C24: "CAP, CERM, 18 pF, 50 V, +/- 5%, C0G/NP0, 0603"
D1: library part LTST-C171GKT, "LED, Green, SMD"
D2: library part SMLP12BC7TT86, "LED, Blue, SMD"
FID1 FID2 FID3: "Fiducial mark.  There is nothing to buy or mount."
H1 H2 H3 H4: library part "MPMS 003 0005 PH", "MACHINE SCREW PAN PHILLIPS M3 5mm"
H5 H6 H7 H8: "Standoff, Hex,25mm Length, M3, Aluminum"
J1: library part PEC04DAAN, "Header, 100mil, 4x2, Tin, TH"
J2 J4 J6: library part PBC02SAAN, "Header, 100mil, 2x1, Gold, TH"
J3: library part PPPC082LJBN-RC, "Receptacle, 100mil, 8x2, Gold, R/A, TH"
J5: library part TSW-110-07-G-D, "Header, 100mil, 10x2, Gold, TH"
Logo1: library part TI_Logo, "Texas Instrument Corporate Signature"
Logo2: library part Pb-Free
Logo3: library part FCC_disclaimer, "FCC_disclaimer"
MIC1 MIC2 MIC3 MIC4: "Wide Bandwidth, Low Noise, Precision Top Port SiSonic Microphone, SMD"
Q1: library part "MMBT2222A, Fairchild Semiconductor", "Transistor, NPN, 40 V, 0.15 A, SOT-23"
R1 R2 R3 R4 R6 R7 R8 R9 R12 R13 R14 R15 R16 R25 R26 R27 R28 R30 R31 R32 R33: "RES, 49.9, 1%, 0.063 W, 0402"
R5: "RES, 10.0 k, 1%, 0.1 W, 0603"
R10 R11 R34 R35 R36 R37: "RES, 2.21 k, 1%, 0.063 W, 0402"
R17 R19 R20 R21 R22 R23: "RES, 0, 5%, 0.1 W, 0603"
R18: "RES, 360, 5%, 0.063 W, 0402"
R24: "RES, 100, 1%, 0.1 W, 0402"
R29: "RES, 2.15 k, 1%, 0.063 W, 0402"
SH1 SH2: "Shunt, 100mil, Gold plated, Black"
TP1 TP2 TP3 TP4 TP5 TP6 TP7 TP8 TP9 TP10 TP11 TP12 TP13 TP14 TP15 TP16 TP17 TP18 TP19 TP20 TP21 TP22 TP23 TP24 TP25 TP26 TP27 TP28 TP29 TP30: library part 5000, "Test Point, Miniature, Red, TH"
U1: "Universal Microphone to 2VRMS Analog input, 24-Bit, 192 kHz Stereo Front-End, DBT0030A"
U2 U4 U6: library part SN74LVC1G125DCKR, "Single Bus Buffer Gate With 3-State Output, DCK0005A"
U3 U5 U7: library part SN74LVC1G126DCKR, "Single Bus Buffer Gate With 3-State Output, DCK0005A"
Y1: "Crystal, 24.576MHz, 18 pF, TH"
ZZ1 ZZ2 ZZ3: library part AssemblyNote

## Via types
v1: diameter 0.635, hole 0.254, Top Copper to Bottom Copper, tented both sides, 86 vias
v2: diameter 6, hole 3.25, Top Copper to Bottom Copper, tented both sides, 4 vias
v3: diameter 0.762, hole 0.381, Top Copper to Bottom Copper, tented both sides, 4 vias

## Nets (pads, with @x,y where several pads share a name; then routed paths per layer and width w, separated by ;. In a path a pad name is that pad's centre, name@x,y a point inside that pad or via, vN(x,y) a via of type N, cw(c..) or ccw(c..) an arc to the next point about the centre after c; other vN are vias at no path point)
3.3V: C1.2 C2.2 C3.2 C4.2 C5.2 C6.2 D2.1 J4.1 J5.16 R5.2 R10.1 R11.1 R17.1 R18.2 R19.1 TP2.1 U2.5 U3.5 U4.5 U5.5 U6.5 U7.5 | length 36.1
  Top Copper w0.254: v1(5.05,48.76) R10.1@5.87,48.75 ; U2.5@33.175,33.49 33.315,33.35 33.76,33.35 ; v1(33.76,31.87) 33.76,33.35 ; C1.2@34.375,33.965 33.76,33.35 ; R19.1@40,46.09 41.92,46.09 v1@41.93,46.1 ; C6.2@42.21,40.08 42.225,40.065 U7.5@42.225,38.54 42.225,37.525 v1@42.31,37.44
  Top Copper w0.35: R11.1@15.5,49.5 v1(16.5,49.5) ; v1(29.25,40.25) R17.1@30.95,40.25 ; R17.1@30.95,40.5 R17.1@31.3,40.5 ; C3.2@39.3,34.75 39.3,34.8 40.25,35.75 U6.5@40.25,36.215 40.25,36.75 40.94,37.44 v1@42.31,37.44
  Copper Layer 4 w2: J4.1@11,25 13.9,25
  Bottom Copper w0.254: D2.1@24,46 v1(24.75,46) ; v1@36.65,36.03 36.77,35.91 36.77,35.02 37.17,34.62 C4.2@37.69,34.62 ; C4.2@37.725,34.615 38.335,34.615 38.47,34.48 38.47,34.13 38.62,33.98 U4.5@38.96,33.98 ; v1@41.97,46.1 42.44,45.63 C2.2@42.44,43.36 ; J5.16@42.225,29.635 J5.16@42.225,30.295 ; U3.5@42.3,42.19 42.3,43.23 C2.2@42.43,43.36 ; v1@42.32,37.43 42.63,37.74 C5.2@43.525,37.74 U5.5@43.525,36.29 ; U5.5@43.52,36.34 43.52,35.57 44.93,34.16 R5.2@44.93,32.66 ; v1(44.25,45.59) R18.2@44.75,45.59
  other v1: 36.7,36.05 42.31,37.42 41.96,46.1
3.3V-USB: J3.15 J3.16 J4.2 | length 9.2
  Top Copper w1: J4.2@8.73,25 J3.15@8.73,31.11 ; J3.15@8.75,31.25 8.73,31.23 J3.15@8.73,31.11 ; J3.16@11.25,31.25 11.39,31.11 J3.16@11.5,31 ; J3.16@11.27,31.11 J3.15@8.73,31.11
AVDD1: C7.2 C8.2 R17.2 U1.8 | length 6
  Top Copper w0.254: C8.2@32.7,41.965 C8.2@32.75,41.915 ; v1@33.5,44.5 v1(33.5,44.515)
  Top Copper w0.5: R17.2@32.75,40.25 32.75,43.75 v1@33.5,44.5
  Bottom Copper w0.254: v1@33.475,44.64 33.5,44.665 U1.8@33.5,45.965
BCK: R2.1 R8.1 R13.1 U4.4 U5.2 | length 68.4
  Top Copper w0.254: R8.1@15.5,42.5 v1(16.5,42.5) ; v1@42.32,31.5 42.45,31.63 54.99,31.63 v1@57.49,34.13
  Copper Layer 3 w0.254: v1(16.5,42.5) 18,42.5 35.5,25 42.25,25 43.57,26.32 43.57,31.1 43.05,31.62 v1@42.35,31.62
  Bottom Copper w0.254: U4.4@40.25,33.94 40.25,33.06 41.69,31.62 v1@42.33,31.62 ; v1@42.35,31.63 42.43,31.63 42.803,32.003 42.803,34.04 U5.2@42.875,34.04 ; R2.1@57.43,36.61 57.43,34.19 v1@57.5,34.12 ; R13.1@57.475,32.865 v1@57.475,34.115
  other v1: 42.34,31.63 57.49,34.1
BCKA: U1.17 U4.2 U5.4 | length 9.2
  Bottom Copper w0.254: U1.17@36.5,40.065 36.5,38.87 37.14,38.23 38.84,38.23 v1@39.58,37.49 ; v1@39.56,37.44 39.6,37.4 U4.2@39.6,36.19 ; v1@39.59,37.46 39.61,37.48 40.7,37.48 41.89,36.29 U5.4@42.225,36.29
  other v1: 39.58,37.46
BCLK-I2X: J3.7 R8.2 | length 6.3
  Top Copper w0.254: J3.7@8.75,41.25 10,42.5 R8.2@14.5,42.5
BCLK-MINIDSP: J5.4 R13.2 | length 2.3
  Bottom Copper w0.254: R13.2@57.475,31.865 57.475,29.645 J5.4@57.51,29.61
BCLK-PSIA: J1.3 R2.2 | length 2.2
  Bottom Copper w0.254: R2.2@57.45,37.61 57.42,37.64 57.42,39.66 J1.3@57.49,39.73
BIAS_MIC1: MIC1.6 R34.2 TP7.1 | length 3.5
  Top Copper w0.254: MIC1.6@70.134,12.884 71.854,12.884 TP7.1@71.92,12.95
  Bottom Copper w0.254: TP7.1@72,13.025 TP7.1@72.05,12.975 ; TP7.1@72.01,12.95 72.05,12.91 R34.2@72.05,11.32
BIAS_MIC2: MIC2.6 R35.2 TP8.1 | length 4
  Top Copper w0.254: MIC2.6@48.884,12.884 50.609,12.884 TP8.1@50.725,13
  Bottom Copper w0.254: TP8.1@50.7,13.025 TP8.1@50.725,13 ; R35.2@50.75,10.95 TP8.1@50.75,13 TP8.1@50.75,13.025
BIAS_MIC3: MIC3.6 R36.2 TP9.1 | length 4
  Top Copper w0.254: MIC3.6@27.671,12.884 29.334,12.884 TP9.1@29.475,13.025
  Bottom Copper w0.254: TP9.1@29.4,12.95 29.475,12.875 R36.2@29.475,10.85
BIAS_MIC4: MIC4.6 R37.2 TP10.1 | length 4.3
  Top Copper w0.254: MIC4.6@6.471,12.884 8.134,12.884 TP10.1@8.25,13
  Bottom Copper w0.254: R37.2@8.175,10.5 8.175,12.925 TP10.1@8.2,12.95
DATA1-MINIDSP: J5.8 R15.2 | length 2.2
  Bottom Copper w0.254: J5.8@52.36,29.66 52.4,29.7 R15.2@52.4,31.89
DATA3-MINIDSP: J5.12 R16.2 | length 15
  Copper Layer 3 w0.254: v1(36.64,37.24) 40.53,33.35 43.51,33.35 J5.12@47.27,29.59
  Bottom Copper w0.254: R16.2@35.51,37.57 36.2,37.57 v1@36.55,37.22
DATA-I2X: J3.9 R7.2 | length 6.8
  Top Copper w0.254: J3.9@8.73,38.73 9.96,37.5 13.25,37.5 R7.2@14.5,38.75
DATA-PSIA: J1.7 R4.2 | length 2
  Bottom Copper w0.254: J1.7@52.41,39.73 52.43,39.71 R4.2@52.43,37.71
DMCLKA: R30.1 R31.1 R32.1 R33.1 U1.20 | length 93.4
  Top Copper w0.254: v1(22.2,19.24) 22.2,20.27 23.2,21.27 30.78,21.27 31.39,20.66 v1(32.59,20.66) v1@32.59,20.67 ; v1@35.04,41.47 35.39,41.12 35.39,39.87 35.76,39.5 35.76,31.65 32.59,28.48 v1@32.59,20.67 ; v1(53.926,21.011) v1@53.915,21 ; v1@72.03,21.9 71.96,21.97 67.984,21.97 65.704,24.25 57.165,24.25 v1@53.915,21 ; v1@32.59,20.67 33.84,20.67 34.17,21 v1@53.915,21
  Bottom Copper w0.254: R33.1@11.175,19.25 11.235,19.19 11.295,19.25 22.17,19.25 v1@22.18,19.24 ; R32.1@32.6,19.25 v1@32.6,20.71 ; U1.20@35,40.065 v1@35,41.44 ; R31.1@53.9,19.25 53.9,20.985 v1(53.926,21.011) ; v1@72.11,21.95 R30.1@73.425,21.95
  other v1: 72.15,21.96 35.04,41.48
DMIN1A/INTA: J5.20 R25.1 R26.1 U1.21 | length 47.7
  Top Copper w0.254: v1@57.81,22.19 v1(64.86,22.19)
  Bottom Copper w0.254: U1.21@34.5,40.065 34.5,35.52 36.16,33.86 36.16,30.52 J5.20@37.04,29.64 ; J5.20@37.23,29.66 38.43,28.46 38.43,25.97 39.79,24.61 45.14,24.61 46.25,23.5 R26.1@46.25,21.675 50.925,21.675 52.75,23.5 56.5,23.5 v1(57.83,22.17) ; v1(64.86,22.19) R25.1@66.31,22.19
DMIN2A/SCKO: R27.1 R28.1 U1.22 U2.2 | length 45.2
  Top Copper w0.254: v1@23.06,23.01 23.075,23.025 24.224,24.204 ; v1(23.06,23.04) 24.224,24.204 ; v1(32.51,36.7) 31.45,36.7 30.64,35.89 30.64,30.62 24.224,24.204 ; v1@32.52,36.66 32.525,36.655 U2.2@32.525,35.74
  Bottom Copper w0.254: R28.1@3.75,21.85 22.92,21.85 R27.1@22.96,21.81 ; R27.1@23.02,21.84 23.02,23 v1@23.04,23.02 ; v1@32.52,36.71 34,38.19 U1.22@34,40.065
DOUT1A: R4.1 R7.1 R15.1 U1.18 | length 77.5
  Top Copper w0.254: R7.1@15.5,38.75 v1@16.37,38.75
  Copper Layer 3 w0.254: v1@16.5,38.75 19.25,38.75 35,23 46.888,23 48.078,24.19 48.53,24.77 48.53,31.81 49.46,32.74 50.92,32.74 v1@52.33,34.15 ; v1(36.61,41.48) 37.62,41.48 38.04,41.06 39.28,41.06 39.57,41.35 48.26,41.35 49.8,39.81 49.8,37.23 v1(50.83,36.2)
  Bottom Copper w0.254: U1.18@36,40.065 36,40.89 36.59,41.48 v1@36.6,41.48 ; v1(50.83,36.2) 50.85,36.2 51.35,36.7 R4.1@52.43,36.7 ; R15.1@52.4,32.89 v1@52.4,34.14 ; v1@52.43,34.12 v1(52.43,34.15) R4.1@52.43,36.7 ; R4.1@52.43,36.7 52.44,36.7 R4.1@52.43,36.71 R4.1@52.43,36.7
  other v1: 16.52,38.73
DOUT2A: R16.1 U1.19 | length 1.5
  Bottom Copper w0.254: R16.1@35.49,38.55 35.5,38.56 U1.19@35.5,40.065
DVDD1: C17.2 C18.2 R19.2 U1.13 U1.14 | length 5.5
  Top Copper w0.254: v1@36.195,44.715 C17.2@37.125,44.715 38.565,44.715 C18.2@38.575,44.705 ; R19.2@38.575,46.015 C18.2@38.575,44.705 ; C18.2@38.6,44.68 C18.2@38.575,44.705
  Bottom Copper w0.254: U1.13@36,45.965 36,44.85 v1@36.14,44.71 ; U1.13@36.025,45.965 U1.14@36.5,45.965
  other v1: 36.14,44.7
GND: C1.1 C2.1 C3.1 C4.1 C5.1 C6.1 C7.1 C8.1 C17.1 C18.1 C19.1 C20.2 C21.1 C22.2 C23.2 C24.2 D1.2 J1.2 J1.4 J1.6 J1.8 J2.2 J3.4 J3.6 J3.8 J3.10 J3.12 J5.1 J5.3 J5.5 J5.7 J5.9 J5.10 J5.11 J5.13 J5.14 J5.17 J5.19 MIC1.1 MIC1.2 MIC1.3 MIC1.5 MIC2.1 MIC2.2 MIC2.3 MIC2.5 MIC3.1 MIC3.2 MIC3.3 MIC3.5 MIC4.1 MIC4.2 MIC4.3 MIC4.5 Q1.2 R20.2 R21.2 R22.2 R23.2 TP1.1 TP5.1 TP6.1 TP27.1 TP28.1 TP29.1 TP30.1 U1.7 U1.12 U1.25 U2.3 U3.3 U4.3 U5.3 U6.3 U7.3 | length 56.4
  Top Copper w0.254: v3@5.49,13.97 5.5,13.98 MIC4.2@5.5,15.092 MIC4.2@5.5,15.12 ; v3@26.74,13.99 26.75,14 MIC3.2@26.75,15.07 ; MIC3.2@26.75,15.092 MIC3.2@26.75,15.07 ; MIC3.2@26.772,15.092 26.761,15.081 MIC3.2@26.75,15.07 ; C8.1@30.8,42.015 31.785,42.015 v1@31.8,42.03 ; C7.1@31.23,43.36 C7.1@31.23,43.46 ; C7.1@31.5,43.5 31.5,42.75 31.77,42.48 v1(31.77,42.02) ; U2.3@31.875,35.74 31.875,34.995 32.27,34.6 32.94,34.6 32.95,34.61 33.733,34.61 33.815,34.692 34.262,34.692 34.34,34.77 C1.1@34.34,35.35 ; C19.1@32.01,53.23 v1@33.03,53.23 ; C20.2@32.5,47.09 32.5,47.94 v1@32.93,48.37 ; C23.2@34.55,52.715 35.535,52.715 35.69,52.87 35.72,52.84 v1(35.72,52.72) ; v1@35.28,43.74 35.705,43.315 C17.1@37.125,43.315 37.905,43.315 38.45,42.77 C18.1@38.56,42.77 ; v1@35.28,43.76 35.31,43.79 35.31,45.02 35.77,45.48 C21.1@35.77,45.58 ; C21.1@35.77,45.61 C21.1@35.77,45.58 ; C21.1@35.95,45.765 35.95,46.98 C22.2@35.97,47 ; C21.1@35.96,45.77 C21.1@35.77,45.58 ; v1(37.72,37.43) 37.72,38.16 38.025,38.465 U6.3@38.95,38.465 ; v1(38.32,52.82) 39.46,52.82 C24.2@39.47,52.81 ; v1@38.62,41.79 38.625,41.795 C18.1@38.625,42.815 ; C6.1@42.225,41.49 43.17,41.49 43.41,41.73 v1(43.41,42.09) ; U7.3@43.525,36.29 44.01,36.29 44.57,35.73 v1@44.57,35.69 ; TP28.1@45.3,15.98 TP28.1@45.3,16.23 ; v1@46.76,50.79 46.775,50.775 D1.2@46.775,49.155 ; v3@48,14 MIC2.2@48,15.092 ; TP27.1@66.54,16.13 TP27.1@66.54,16.21 ; MIC1.2@69.2,15.08 MIC1.2@69.25,15.03 ; MIC1.2@69.25,15.092 MIC1.2@69.25,15.03 ; v3@69.26,14.01 69.25,14.02 MIC1.2@69.25,15.03
  Top Copper w0.5: 30.265,42.015 C8.1@30.8,42.015 ; 30.515,43.515 C7.1@31.3,43.515
  Top Copper w0.6: C17.1@37.125,43.25 38.45,43.25
  Bottom Copper w0.254: R23.2@11.475,16.25 v1@12.66,16.25 ; v1@31.77,42 32.5,41.27 U1.25@32.5,40.065 ; R22.2@32.875,16.25 v1@34.23,16.25 ; U1.7@33,45.965 v1@33,48.34 ; v1@35.29,43.77 35.495,43.975 35.495,45.965 U1.12@35.5,45.965 ; v1@37.69,37.43 37.725,37.395 C4.1@37.725,36.015 ; U4.3@40.25,36.19 40.25,35.19 41.41,34.03 ; v1@40.3,40.46 40.3,40.09 40.45,39.94 U3.3@41,39.94 ; 41.42,34.05 42.215,34.05 U5.3@42.225,34.04 ; v1@43.34,42.01 v1@43.344,42.015 ; v1@43.35,42.02 43.41,42.08 v1(43.41,42.09) 43.84,42.52 C2.1@43.84,43.36 ; C5.1@43.525,39.14 44.49,39.14 v1@44.5,39.13 ; R21.2@54.15,16.25 v1@55.15,16.25 ; TP27.1@66.49,16.23 67.81,17.55 R20.2@69.125,17.55
  other v1: 12.67,16.24 34.26,16.26 55.16,16.25 29.25,33.5 32.94,34.61 41.5,34.75 44.57,35.7 44.57,39.15 40.31,40.5 38.62,41.86 35.28,43.75 28.5,45.75 32.97,48.38 46.79,50.8 25.75,51 33.03,53.24
  other v2: 4,4 71,4 19,54 71,54
  other v3: 5.5,13.97 26.74,13.98 48,13.99 69.24,13.98
LRCK: R3.1 R6.1 R14.1 U6.4 U7.2 | length 84.2
  Top Copper w0.254: R6.1@15.5,35 v1(16.5,35) ; U6.4@38.95,36.215 38.555,36.215 38.25,35.91 38.25,32.66 39.16,31.75 40.7,31.75 42.875,33.925 42.875,34.33 ; U7.2@42.875,36.29 42.875,34.33 ; v1@45.7,34.36 v1(45.73,34.33) 42.875,34.33
  Copper Layer 3 w0.254: v1(16.5,35) 20.5,35 34.5,21 48.856,21 53.106,25.25 53.71,26.16 53.71,31.71 54.85,32.85 v1@54.85,34.09 ; v1@45.81,34.36 50.84,34.36 52.294,35.814 53.206,35.814 v1(54.92,34.1)
  Bottom Copper w0.254: R14.1@54.925,32.865 v1@54.925,34.115 ; v1@54.93,34.12 R3.1@54.93,36.71
LRCKA: U1.16 U6.2 U7.4 | length 9.6
  Top Copper w0.254: v1@39.59,39.59 39.6,39.58 U6.2@39.6,38.465 ; v1@43.5,40.24 43.525,40.215 U7.4@43.525,38.54
  Copper Layer 3 w0.254: v1@39.65,39.58 39.659,39.589 40.489,39.589 40.95,40.05 v1@43.46,40.05
  Bottom Copper w0.254: U1.16@37,40.065 39.165,40.065 v1@39.57,39.66 ; v1(39.63,39.59) v1@39.63,39.628
  other v1: 43.52,40.06
LRCLK-I2X: J3.11 R6.2 | length 5.9
  Top Copper w0.25: J3.11@9,36 10,35 R6.2@14.5,35
LRCLK-MINIDSP: J5.6 R14.2 | length 2.3
  Bottom Copper w0.254: J5.6@54.91,29.56 54.925,29.575 R14.2@54.925,31.865
LRCLK-PSIA: J1.5 R3.2 | length 2
  Bottom Copper w0.254: R3.2@54.93,37.73 54.92,37.74 54.92,39.7 J1.5@54.95,39.73
MCLK-I2X: J3.3 R9.2 | length 7
  Top Copper w0.254: J3.3@8.73,46.35 10.08,45 13,45 R9.2@14.5,46.5
MCLK-MINIDSP: J5.2 R12.2 | length 2.2
  Bottom Copper w0.254: J5.2@59.92,29.68 60,29.76 R12.2@60,31.865
MCLK-PSIA: J1.1 R1.2 | length 2.2
  Bottom Copper w0.254: R1.2@59.96,37.58 59.97,37.59 59.97,39.67 J1.1@60.03,39.73
MICBIAS-A: C19.2 J6.2 R29.2 U1.5 | length 15.6
  Top Copper w0.254: C19.2@32,51.85 32,51.06 v1(32.64,50.42) ; C19.2@32.01,51.85 C19.2@32.01,51.83 C19.2@32.11,51.73
  Copper Layer 3 w0.254: J6.2@26.5,48.77 v1(28.16,50.43) v1@32.63,50.43
  Bottom Copper w0.254: R29.2@28.075,52.5 28.235,52.34 28.16,52.265 v1(28.16,50.43) ; U1.5@32,45.965 32,49 32.63,49.63 v1@32.63,50.43
NetC9_2: C9.2 MIC1.4 TP11.1 | length 5
  Top Copper w0.254: TP11.1@66.5,12.975 66.591,12.884 MIC1.4@68.366,12.884
  Bottom Copper w0.254: TP11.1@66.5,12.975 66.5,11.9 67.08,11.32 C9.2@68.31,11.32
NetC10_2: C10.2 MIC2.4 TP12.1 | length 5.4
  Top Copper w0.254: TP12.1@45.25,12.975 45.341,12.884 MIC2.4@47.116,12.884
  Bottom Copper w0.254: TP12.1@45.2,12.95 45.2,11.5 45.8,10.9 C10.2@46.975,10.9
NetC11_2: C11.2 MIC3.4 TP13.1 | length 5.3
  Top Copper w0.254: TP13.1@24,13 24.116,12.884 MIC3.4@25.903,12.884
  Bottom Copper w0.254: TP13.1@23.975,12.975 23.975,11.625 24.575,11.025 C11.2@25.775,11.025
NetC12_2: C12.2 MIC4.4 TP14.1 | length 5.5
  Top Copper w0.254: TP14.1@2.75,13 2.866,12.884 MIC4.4@4.703,12.884
  Bottom Copper w0.254: TP14.1@2.725,12.975 2.725,11.875 3.475,11.125 4.45,11.125 C12.2@4.7,11.375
